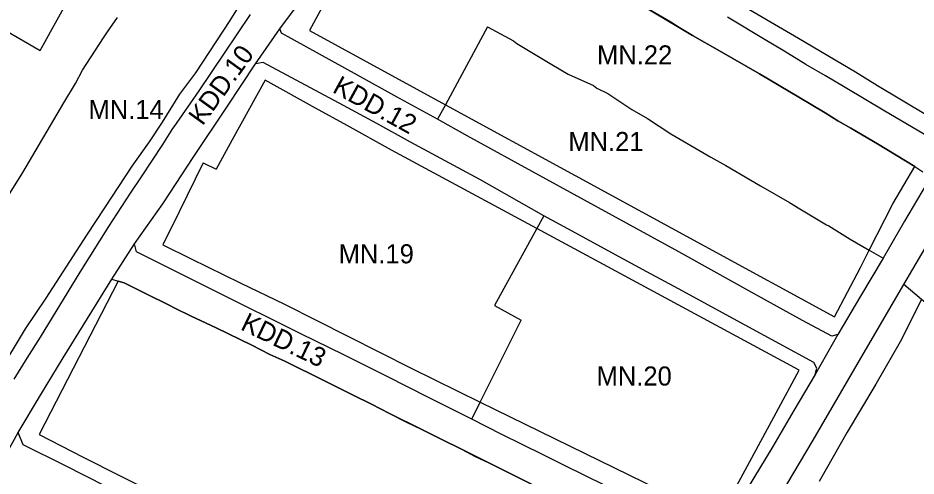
# Model space of a CAD drawing. Extents: x 7425067 to 7426806, y 5549054 to 5550619.
# Drawn here: x 7425775.6 to 7426010.9, y 5549856.3 to 5549976.3 of the extents above; entities that cross this region are included whole.
import ezdxf

# ---------------------------------------------------------------- set-up
doc = ezdxf.new("R2010")
doc.units = 0
for name, color, linetype in [('LIN_Linia Zabudowy Nieprzekraczalna', 7, 'Continuous'), ('LIN_linia zabudowy obowiązująca', 7, 'Continuous'), ('LIN_linie_rozgraniczajace', 7, 'Continuous'), ('TXT_Oznaczenia_przeznaczen', 7, 'Continuous')]:
    doc.layers.add(name, color=color, linetype=linetype)

msp = doc.modelspace()

# ---------------------------------------------------------------- linework, layer by layer
at = {"layer": 'LIN_Linia Zabudowy Nieprzekraczalna'}
for points in [[(7425742.7389, 5549884.8292), (7425754.78, 5549877.53), (7425763.82, 5549872.05), (7425777.59, 5549894.86), (7425782.97, 5549902.92), (7425793.7, 5549919.37), (7425798.37, 5549926.6), (7425805.55, 5549937.49), (7425810.05, 5549943.84), (7425813.5, 5549948.98), (7425818.04, 5549956.33), (7425822.22, 5549961.9), (7425831.24, 5549975.65), (7425835.44, 5549982.46), (7425845.17, 5549996.67), (7425848.22, 5550001.39), (7425860.25, 5550019.29)], [(7425862.3081, 5549992.0502), (7425852.01, 5549973.01), (7425887.6133, 5549953.5801), (7425989.492, 5549897.9817)], [(7425840.3535, 5549960.0039), (7425831.73, 5549944.37), (7425827.5022, 5549936.7053)], [(7425980.2392, 5549884.0122), (7425911.5114, 5549921.1466), (7425873.49, 5549941.69), (7425861.89, 5549948.1), (7425853.53, 5549952.69), (7425840.3535, 5549960.0039)], [(7425824.1545, 5549938.3756), (7425817.84, 5549925.54), (7425813.56, 5549916.84)], [(7425824.1545, 5549938.3756), (7425827.5022, 5549936.7053)], [(7425989.492, 5549897.9817), (7425996.29, 5549910.89), (7425998.6213, 5549915.476), (7426004.81, 5549927.65), (7426010.59, 5549937.36)], [(7425813.56, 5549916.84), (7425820.98, 5549913.17), (7425833.83, 5549906.92), (7425845.48, 5549901.28)], [(7425801.8723, 5549907.3701), (7425781.18, 5549867.15), (7425792.69, 5549861.24), (7425821.44, 5549846.75), (7425833.18, 5549840.94), (7425839.1, 5549837.99), (7425845.79, 5549834.72), (7425857.5, 5549828.65), (7425868.39, 5549823.29), (7425875.97, 5549819.39), (7425885.52, 5549814.72), (7425893.57, 5549810.92), (7425904.63, 5549805.55), (7425904.8856, 5549806.0772)], [(7425821, 5549898.215), (7425816.715, 5549900.285), (7425815.01, 5549901.11), (7425809.24, 5549904), (7425803.44, 5549906.87), (7425801.8723, 5549907.3701)], [(7426012.3076, 5549902.588), (7426006.73, 5549891.48), (7426000.31, 5549880.37), (7425992.85, 5549867.81), (7425985.5251, 5549854.844)], [(7425845.48, 5549901.28), (7425878.63, 5549884.56), (7425896.7396, 5549875.6767), (7425959.1857, 5549845.0449)], [(7425937.19, 5549840.97), (7425931.34, 5549843.63), (7425924.075, 5549847.175), (7425916.81, 5549850.72), (7425913.24, 5549852.55), (7425909.79, 5549854.33), (7425899, 5549859.75), (7425891.99, 5549863.26), (7425886.51, 5549865.975), (7425881.03, 5549868.69), (7425872.94, 5549872.69), (7425868.2, 5549875.09), (7425863.46, 5549877.49), (7425859.61, 5549879.4), (7425855.92, 5549881.24), (7425845.49, 5549886.35), (7425841.62, 5549888.14), (7425836.88, 5549890.54), (7425827.51, 5549895.12), (7425821, 5549898.215)], [(7425959.1857, 5549845.0449), (7425974.23, 5549872.89), (7425980.2392, 5549884.0122)]]:
    msp.add_lwpolyline(points, dxfattribs=at)
at = {"layer": 'LIN_linia zabudowy obowiązująca'}
for points in [[(7425771.07, 5549973.79), (7425781.44, 5549967.75), (7425838.25, 5550070.38), (7425827.66, 5550076.24)], [(7425893.9, 5550021.45), (7425920.1, 5550006.36), (7425924.87, 5550003.45), (7425942.08, 5549993.19), (7425946.76, 5549990.58), (7425980.13, 5549971.02), (7425987.76, 5549966.48), (7425995.01, 5549962.2), (7426000.79, 5549958.61), (7426013.79, 5549950.82), (7426019.11, 5549959.62), (7426025.8248, 5549970.7272), (7426030.7315, 5549978.8436)], [(7426010.59, 5549937.36), (7426000.75, 5549943.29), (7425993.84, 5549947.42), (7425990.41, 5549949.38), (7425987.07, 5549951.43), (7425980.16, 5549955.59), (7425969.84, 5549961.68), (7425959.38, 5549967.72), (7425952.35, 5549971.75), (7425948.86, 5549973.84), (7425946.62, 5549975.18), (7425938.68, 5549979.84), (7425932.98, 5549983.21), (7425928.33, 5549985.92), (7425923.28, 5549988.93), (7425917.99, 5549991.99), (7425907.79, 5549998.04), (7425897.42, 5550004.16), (7425889.48, 5550009.02), (7425879.6191, 5550014.9366)]]:
    msp.add_lwpolyline(points, dxfattribs=at)
at = {"layer": 'LIN_linie_rozgraniczajace'}
for points in [[(7425844.24, 5549973.42), (7425849.1, 5549979.97)], [(7425938.68, 5549979.84), (7425948.86, 5549973.84)], [(7425836.48, 5549977.19), (7425829.63, 5549967.12)], [(7425799.07, 5549972.68), (7425801.69, 5549976.45)], [(7425971.8, 5549970.34), (7425961.47, 5549976.55)], [(7425798.05, 5549971.1), (7425799.07, 5549972.68)], [(7425837.87, 5549964.3), (7425844.24, 5549973.42)], [(7425844.61, 5549972.31), (7425844.24, 5549973.42)], [(7425864.55, 5549961.35), (7425844.61, 5549972.31)], [(7425898.61, 5549973.94), (7425887.6133, 5549953.5801), (7425885.55, 5549949.76)], [(7425898.61, 5549973.94), (7425905.46, 5549970.27)], [(7425948.86, 5549973.84), (7425952.35, 5549971.75)], [(7425792.52, 5549962.6), (7425798.05, 5549971.1)], [(7425905.46, 5549970.27), (7425906.33, 5549969.62)], [(7425906.33, 5549969.62), (7425911.065, 5549966.725)], [(7425952.35, 5549971.75), (7425959.38, 5549967.72)], [(7425975.645, 5549968.005), (7425971.8, 5549970.34)], [(7425959.38, 5549967.72), (7425969.84, 5549961.68)], [(7425979.49, 5549965.67), (7425975.645, 5549968.005)], [(7425829.63, 5549967.12), (7425823, 5549957.23)], [(7425911.065, 5549966.725), (7425911.54, 5549966.45)], [(7425911.54, 5549966.45), (7425915.48, 5549964.14)], [(7425982.04, 5549964.13), (7425979.49, 5549965.67)], [(7425790.68, 5549959.16), (7425792.52, 5549962.6)], [(7425834.09, 5549958.62), (7425837.87, 5549964.3)], [(7425839.81, 5549964.65), (7425837.87, 5549964.3)], [(7425860.93, 5549953.33), (7425839.81, 5549964.65)], [(7425915.48, 5549964.14), (7425919.72, 5549961.62)], [(7425987.195, 5549961.11), (7425982.04, 5549964.13)], [(7425874.92, 5549955.57), (7425864.55, 5549961.35)], [(7425919.72, 5549961.62), (7425926.35, 5549958.58)], [(7425969.84, 5549961.68), (7425980.16, 5549955.59)], [(7425992.35, 5549958.09), (7425987.195, 5549961.11)], [(7425787.61, 5549954.08), (7425790.68, 5549959.16)], [(7425830.31, 5549952.94), (7425834.09, 5549958.62)], [(7425926.35, 5549958.58), (7425927.24, 5549957.93)], [(7425927.24, 5549957.93), (7425930.18, 5549956.48)], [(7426002.67, 5549951.9), (7425992.35, 5549958.09)], [(7425823, 5549957.23), (7425816.46, 5549947.77)], [(7425885.55, 5549949.76), (7425874.92, 5549955.57)], [(7425930.18, 5549956.48), (7425936.47, 5549952.34)], [(7425980.16, 5549955.59), (7425987.07, 5549951.43)], [(7425776.93, 5549935.78), (7425787.61, 5549954.08)], [(7425869.6, 5549948.64), (7425860.93, 5549953.33)], [(7425821.48, 5549939.71), (7425830.31, 5549952.94)], [(7425936.47, 5549952.34), (7425940.53, 5549949.97)], [(7425987.07, 5549951.43), (7425990.41, 5549949.38)], [(7426017.12, 5549943.41), (7426002.67, 5549951.9)], [(7425878.45, 5549943.79), (7425869.6, 5549948.64)], [(7425893.26, 5549945.43), (7425885.55, 5549949.76)], [(7425940.53, 5549949.97), (7425946.67, 5549945.98)], [(7425990.41, 5549949.38), (7425993.84, 5549947.42)], [(7425816.14, 5549947.32), (7425813.455, 5549943.195)], [(7425816.46, 5549947.77), (7425816.14, 5549947.32)], [(7425993.84, 5549947.42), (7426000.75, 5549943.29)], [(7425896.65, 5549933.97), (7425878.45, 5549943.79)], [(7425898.72, 5549942.47), (7425893.26, 5549945.43)], [(7425946.67, 5549945.98), (7425957.14, 5549939.84)], [(7425813.455, 5549943.195), (7425810.77, 5549939.07)], [(7425906.69, 5549938.12), (7425898.72, 5549942.47)], [(7426000.75, 5549943.29), (7426010.59, 5549937.36)], [(7425810.77, 5549939.07), (7425807.885, 5549934.72)], [(7425815.395, 5549930.39), (7425821.48, 5549939.71)], [(7425957.14, 5549939.84), (7425961.01, 5549937.69)], [(7425927.68, 5549926.57), (7425906.69, 5549938.12)], [(7425961.01, 5549937.69), (7425967.56, 5549933.77)], [(7426010.59, 5549937.36), (7426012.68, 5549935.98)], [(7425769.12, 5549923.52), (7425776.93, 5549935.78)], [(7425807.885, 5549934.72), (7425805, 5549930.37)], [(7425913.34, 5549924.48), (7425896.65, 5549933.97)], [(7425967.56, 5549933.77), (7425970.11, 5549932.36)], [(7425970.11, 5549932.36), (7425977.73, 5549927.94)], [(7426013.56, 5549932.67), (7426007.895, 5549923.035)], [(7425805, 5549930.37), (7425799.29, 5549921.71)], [(7425813.59, 5549927.64), (7425815.395, 5549930.39)], [(7425806.15, 5549917.13), (7425813.59, 5549927.64)], [(7425977.73, 5549927.94), (7425980.42, 5549926.3)], [(7425948.76, 5549915), (7425927.68, 5549926.57)], [(7425980.42, 5549926.3), (7425987.44, 5549922.11)], [(7426007.64, 5549906.46), (7426019.44, 5549926.55)], [(7425913.34, 5549924.48), (7425911.5114, 5549921.1466), (7425900.46, 5549901)], [(7425921.75, 5549919.96), (7425913.34, 5549924.48)], [(7426007.895, 5549923.035), (7426002.23, 5549913.4)], [(7425799.29, 5549921.71), (7425791.81, 5549909.73)], [(7425987.44, 5549922.11), (7425988.04, 5549921.81)], [(7425988.04, 5549921.81), (7425993.66, 5549918.33)], [(7425931.18, 5549914.8), (7425921.75, 5549919.96)], [(7425993.66, 5549918.33), (7425998.6213, 5549915.476), (7426002.23, 5549913.4)], [(7425800.18, 5549907.91), (7425806.15, 5549917.13)], [(7425806.64, 5549915.05), (7425806.15, 5549917.13)], [(7425827.3, 5549904.74), (7425806.64, 5549915.05)], [(7425940.38, 5549909.78), (7425931.18, 5549914.8)], [(7425958.03, 5549909.84), (7425948.76, 5549915)], [(7426002.23, 5549913.4), (7425996.305, 5549903.38)], [(7425791.81, 5549909.73), (7425781.39, 5549892.72)], [(7425948.62, 5549905.31), (7425940.38, 5549909.78)], [(7425967.11, 5549904.78), (7425958.03, 5549909.84)], [(7425787.46, 5549887.25), (7425800.18, 5549907.91)], [(7425800.18, 5549907.91), (7425801.8723, 5549907.3701), (7425803.44, 5549906.87)], [(7425803.44, 5549906.87), (7425809.24, 5549904)], [(7425997.61, 5549889.25), (7426007.64, 5549906.46)], [(7426019.55, 5549896.58), (7426012.3076, 5549902.588), (7426007.64, 5549906.46)], [(7425809.24, 5549904), (7425815.01, 5549901.11)], [(7425849.72, 5549893.54), (7425827.3, 5549904.74)], [(7425966.15, 5549895.8), (7425948.62, 5549905.31)], [(7425975.26, 5549900.25), (7425967.11, 5549904.78)], [(7425996.305, 5549903.38), (7425990.38, 5549893.36)], [(7425815.01, 5549901.11), (7425816.715, 5549900.285)], [(7425816.715, 5549900.285), (7425821, 5549898.215)], [(7425900.46, 5549901), (7425907.42, 5549897.12)], [(7425981.15, 5549897.07), (7425975.26, 5549900.25)], [(7425821, 5549898.215), (7425823.58, 5549896.97)], [(7425823.58, 5549896.97), (7425827.51, 5549895.12)], [(7425894.49, 5549871.16), (7425896.7396, 5549875.6767), (7425907.42, 5549897.12)], [(7425988.84, 5549892.94), (7425981.15, 5549897.07)], [(7425827.51, 5549895.12), (7425836.88, 5549890.54)], [(7425984.08, 5549886.01), (7425966.15, 5549895.8)], [(7425781.39, 5549892.72), (7425777.9, 5549887.14)], [(7425860.94, 5549888.01), (7425849.72, 5549893.54)], [(7425990.38, 5549893.36), (7425984.42, 5549882.91)], [(7425990.38, 5549893.36), (7425988.84, 5549892.94)], [(7425836.88, 5549890.54), (7425841.62, 5549888.14)], [(7425781.555, 5549877.49), (7425787.46, 5549887.25)], [(7425841.62, 5549888.14), (7425845.49, 5549886.35)], [(7425866.53, 5549885.22), (7425860.94, 5549888.01)], [(7425991.11, 5549877.98), (7425997.61, 5549889.25)], [(7425777.9, 5549887.14), (7425774.54, 5549881.69)], [(7425845.49, 5549886.35), (7425855.92, 5549881.24)], [(7425872.12, 5549882.43), (7425866.53, 5549885.22)], [(7425984.9, 5549884.54), (7425984.08, 5549886.01)], [(7425984.42, 5549882.91), (7425978.9, 5549873.48)], [(7425984.42, 5549882.91), (7425984.9, 5549884.54)], [(7425855.92, 5549881.24), (7425859.61, 5549879.4)], [(7425883.305, 5549876.795), (7425872.12, 5549882.43)], [(7425859.61, 5549879.4), (7425863.46, 5549877.49)], [(7425983.91, 5549865.66), (7425991.11, 5549877.98)], [(7425775.65, 5549867.73), (7425781.555, 5549877.49)], [(7425863.46, 5549877.49), (7425868.2, 5549875.09)], [(7425894.49, 5549871.16), (7425883.305, 5549876.795)], [(7425868.2, 5549875.09), (7425872.94, 5549872.69)], [(7425978.9, 5549873.48), (7425973.38, 5549864.05)], [(7425872.94, 5549872.69), (7425877.54, 5549870.33)], [(7425902.41, 5549867.2), (7425894.49, 5549871.16)], [(7425877.54, 5549870.33), (7425881.03, 5549868.69)], [(7425881.03, 5549868.69), (7425886.51, 5549865.975)], [(7425770.44, 5549858.34), (7425775.65, 5549867.73)], [(7425777, 5549864.45), (7425775.65, 5549867.73)], [(7425907.73, 5549864.6), (7425902.41, 5549867.2)], [(7425787.855, 5549859.015), (7425777, 5549864.45)], [(7425886.51, 5549865.975), (7425891.99, 5549863.26)], [(7425913.18, 5549861.83), (7425907.73, 5549864.6)], [(7425973.38, 5549864.05), (7425966.665, 5549852.915)], [(7425977.03, 5549854.05), (7425983.91, 5549865.66)], [(7425891.99, 5549863.26), (7425895.36, 5549861.43)], [(7425895.36, 5549861.43), (7425899, 5549859.75)], [(7425918.6, 5549859.16), (7425913.18, 5549861.83)], [(7425798.71, 5549853.58), (7425787.855, 5549859.015)], [(7425899, 5549859.75), (7425909.79, 5549854.33)], [(7425924.14, 5549856.46), (7425918.6, 5549859.16)], [(7425929.25, 5549853.88), (7425924.14, 5549856.46)]]:
    msp.add_lwpolyline(points, dxfattribs=at)

# ---------------------------------------------------------------- texts
at = {"layer": 'TXT_Oznaczenia_przeznaczen'}
for s, rotation, p in [('KDD.10', 54.118727, (7425823.9609, 5549947.8549)), ('KDD.12', 331.188164, (7425857.7231, 5549956.9975)), ('KDD.13', 334.29007, (7425833.6407, 5549894.776))]:
    msp.add_text(s, height=5, rotation=rotation, dxfattribs=at).set_placement(p)
for s, p in [('MN.22', (7425927.3211, 5549964.1238)), ('MN.14', (7425794.0906, 5549949.81)), ('MN.21', (7425919.7967, 5549941.4285)), ('MN.19', (7425859.6315, 5549912.0119)), ('MN.20', (7425927.198, 5549879.9979))]:
    msp.add_text(s, height=5, dxfattribs=at).set_placement(p)

doc.saveas('drawing.dxf')
